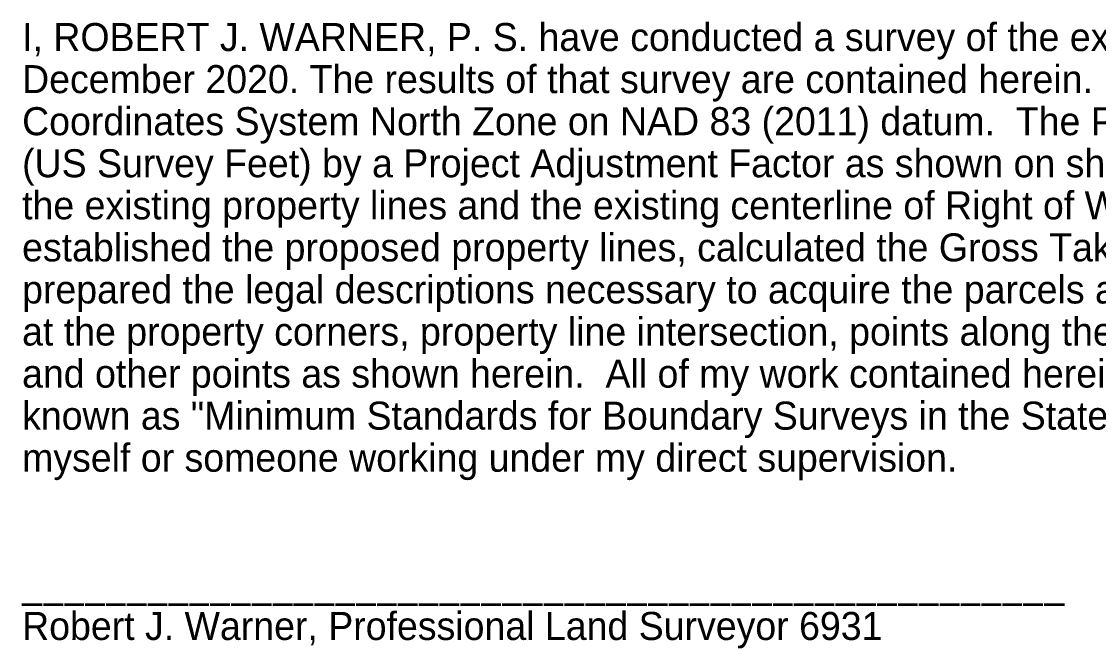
# Model space of a CAD drawing. Extents: x -1 to 48.3, y -9.3 to 22.
# Drawn here: x 36.07 to 41.45, y -8.08 to -4.95 of the extents above; entities that cross this region are included whole.
import ezdxf

# ---------------------------------------------------------------- set-up
doc = ezdxf.new("R2010")
doc.units = 0
doc.layers.add('GM_X_Township', color=7, linetype='Continuous')

msp = doc.modelspace()

# ---------------------------------------------------------------- texts
at = {"layer": 'GM_X_Township'}
for s, p in [('I, ROBERT J. WARNER, P. S. have conducted a survey of the existing conditions for the Ohio Department of Transportation in November and ', (36.0722, -5.0928)), ('December 2020. The results of that survey are contained herein.  The horizontal coordinates expressed herein are based on the Ohio State Plane ', (36.0722, -5.3028)), ('Coordinates System North Zone on NAD 83 (2011) datum.  The Project Coordinates (US Survey Feet) are relative to State Plane Grid Coordinates', (36.0722, -5.5128)), ('(US Survey Feet) by a Project Adjustment Factor as shown on sheets 3 through 9.  As a part of this project I have reestablished the locations of', (36.0722, -5.7228)), ('the existing property lines and the existing centerline of Right of Way for property takes contained herein.  As a part of this project I have', (36.0722, -5.9328)), ('established the proposed property lines, calculated the Gross Take, present roadway occupied (PRO), Net Take and Net Residue; as well as', (36.0722, -6.1428)), ('prepared the legal descriptions necessary to acquire the parcels as shown herein.  As a part of this work I have set right of way monuments', (36.0722, -6.3528)), ('at the property corners, property line intersection, points along the right of way and/or angle points on the right of way, Section Corners', (36.0722, -6.5628)), ('and other points as shown herein.  All of my work contained herein was conducted in accordance with Ohio Administrative Code 4733-37 commonly', (36.0722, -6.7728)), ('known as "Minimum Standards for Boundary Surveys in the State of Ohio" unless noted.  The words I and my as used herein are to mean either', (36.0722, -6.9828)), ('myself or someone working under my direct supervision.', (36.0722, -7.1928)), ('__________________________________________________                                        ', (36.0722, -7.8228)), ('Robert J. Warner, Professional Land Surveyor 6931                                        Date:                  ', (36.0722, -8.0328))]:
    msp.add_text(s, height=0.14, dxfattribs=at).set_placement(p)

doc.saveas('drawing.dxf')
